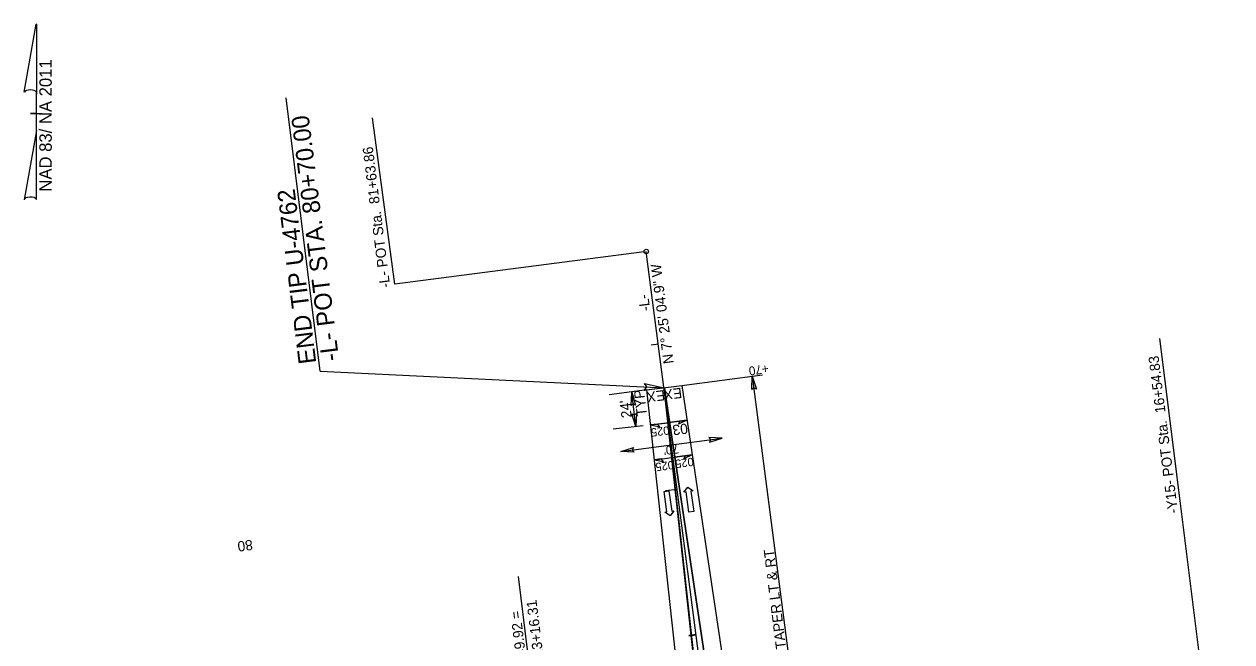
# Model space of a CAD drawing. Extents: x 2367848 to 2369479, y 800728 to 808616.
# Drawn here: x 2367890 to 2368715, y 808194 to 808616 of the extents above; entities that cross this region are included whole.
import ezdxf

# ---------------------------------------------------------------- set-up
doc = ezdxf.new("R2010")
doc.units = 0
for name, color, linetype in [('Prop Dimension', 7, 'Continuous'), ('Prop EOT', 7, 'Continuous'), ('Prop Horizontal Alignment', 7, 'Continuous'), ('Prop Horizontal Alignment Direction Label', 7, 'Continuous'), ('Prop Horizontal Alignment Station Label', 7, 'Continuous'), ('Prop Horizontal Alignment Tick Label', 7, 'Continuous'), ('Prop Horizontal Alignment Tick Large', 7, 'Continuous'), ('Prop Horizontal Alignment Tick Small', 7, 'Continuous'), ('Prop Lane Arrow CELL', 7, 'Continuous'), ('Prop Lane Lines', 7, 'Continuous'), ('Prop North Arrow NAD83 for Plan Sheets CELL', 7, 'Continuous'), ('Prop Paint Stripe', 7, 'Continuous'), ('Prop Superelevation  Arrow CELL', 7, 'Continuous'), ('Prop Superelevation Label', 7, 'Continuous'), ('Prop Terminator CELL', 7, 'Continuous')]:
    doc.layers.add(name, color=color, linetype=linetype)

msp = doc.modelspace()

# ---------------------------------------------------------------- linework, layer by layer
at = {"layer": 'Prop Dimension'}
for p, q in [((2368092.34, 808378.48), (2368069.05, 808565.34)), ((2368092.34, 808378.48), (2368327.36, 808367.26)), ((2368339.44, 808368.83), (2368394.74, 808376.03)), ((2368387.64, 808375.11), (2368426.37, 808077.62)), ((2368315.58, 808365.73), (2368289.84, 808362.37)), ((2368308.04, 808340.68), (2368305.28, 808364.22)), ((2368313.14, 808341.28), (2368292.68, 808338.88)), ((2368297.74, 808323.71), (2368367.15, 808332.75))]:
    msp.add_line(p, q, dxfattribs=at)
at = {"layer": 'Prop EOT'}
for p, q in [((2368315.58, 808365.73), (2368339.44, 808368.83)), ((2368348.25, 808067.45), (2368315.58, 808365.73)), ((2368339.44, 808368.83), (2368383.94, 808072.1))]:
    msp.add_line(p, q, dxfattribs=at)
at = {"layer": 'Prop Horizontal Alignment'}
msp.add_line((2368427.27, 807599.89), (2368315.24, 808460.34), dxfattribs=at)
at = {"layer": 'Prop Horizontal Alignment Station Label'}
for p, q in [((2368143.33, 808437.96), (2368128.09, 808551.49)), ((2368313.76, 808460.14), (2368143.33, 808437.96)), ((2368680.11, 808289.96), (2368666.29, 808400.85)), ((2368715.42, 808006.91), (2368680.11, 808289.96)), ((2368243.01, 808116.67), (2368227.83, 808238.43))]:
    msp.add_line(p, q, dxfattribs=at)
msp.add_circle((2368315.24, 808460.34), 1.5, dxfattribs=at)
at = {"layer": 'Prop Horizontal Alignment Tick Large'}
msp.add_line((2368336.4, 808297.85), (2368328.47, 808296.81), dxfattribs=at)
at = {"layer": 'Prop Horizontal Alignment Tick Small'}
for p, q in [((2368323.49, 808397.01), (2368318.53, 808396.36)), ((2368349.31, 808198.68), (2368344.35, 808198.04)), ((2368349.37, 808198.26), (2368344.41, 808197.61))]:
    msp.add_line(p, q, dxfattribs=at)
at = {"layer": 'Prop Lane Arrow CELL'}
for p, q in [((2368327.42, 808296.46), (2368330.69, 808296.92)), ((2368329.37, 808282.6), (2368327.42, 808296.46)), ((2368330.69, 808296.92), (2368332.64, 808283.06)), ((2368340.98, 808295.87), (2368343.6, 808299.43)), ((2368343.6, 808299.43), (2368347.21, 808296.75)), ((2368347.21, 808296.75), (2368345.73, 808296.55)), ((2368345.73, 808296.55), (2368347.68, 808282.68)), ((2368342.46, 808296.08), (2368340.98, 808295.87)), ((2368344.42, 808282.22), (2368342.46, 808296.08)), ((2368327.89, 808282.39), (2368329.37, 808282.6)), ((2368331.5, 808279.72), (2368327.89, 808282.39)), ((2368334.13, 808283.27), (2368331.5, 808279.72)), ((2368332.64, 808283.06), (2368334.13, 808283.27)), ((2368347.68, 808282.68), (2368344.42, 808282.22))]:
    msp.add_line(p, q, dxfattribs=at)
at = {"layer": 'Prop Lane Lines'}
for p, q in [((2368360.2, 808068.57), (2368327.53, 808366.85)), ((2368327.59, 808366.86), (2368372.04, 808070.55))]:
    msp.add_line(p, q, dxfattribs=at)
at = {"layer": 'Prop North Arrow NAD83 for Plan Sheets CELL'}
for p, q in [((2367890.15, 808569.2), (2367898.35, 808615.55)), ((2367898.4, 808615.55), (2367898.35, 808615.55)), ((2367898.4, 808615.55), (2367898.35, 808615.55)), ((2367898.4, 808615.55), (2367898.4, 808567.75)), ((2367898.4, 808542.95), (2367898.4, 808569.15)), ((2367898.4, 808567.75), (2367898.4, 808569.1)), ((2367894.4, 808554.55), (2367894.35, 808554.55)), ((2367897.95, 808554.55), (2367894.4, 808554.55)), ((2367894.45, 808554.55), (2367902.45, 808554.55)), ((2367898.4, 808542.95), (2367890.05, 808495.7)), ((2367898.45, 808495.9), (2367898.4, 808542.95))]:
    msp.add_line(p, q, dxfattribs=at)
for centre, start_param, end_param in [((2367894.29, 808568.71), 0.216388, 2.908219), ((2367894.29, 808495.54), 0.201328, 3.141593)]:
    msp.add_ellipse(centre, major_axis=(4.23, -0.03), ratio=0.461098, start_param=start_param, end_param=end_param, dxfattribs=at)
at = {"layer": 'Prop Paint Stripe'}
for p, q in [((2368327.59, 808366.86), (2368327.53, 808366.85)), ((2368327.59, 808366.86), (2368327.53, 808366.85)), ((2368327.53, 808366.85), (2368349.27, 808168.42)), ((2368372.04, 808070.55), (2368327.59, 808366.86)), ((2368372.04, 808070.55), (2368327.59, 808366.86))]:
    msp.add_line(p, q, dxfattribs=at)
msp.add_lwpolyline([(2368327.53, 808366.85), (2368349.27, 808168.42), (2368360.2, 808068.57)], dxfattribs=at)
at = {"layer": 'Prop Superelevation  Arrow CELL'}
for p, q in [((2368318.19, 808341.86), (2368330.09, 808343.41)), ((2368343, 808345.09), (2368331.1, 808343.54)), ((2368346.56, 808321.36), (2368334.66, 808319.81)), ((2368320.8, 808318), (2368332.7, 808319.55))]:
    msp.add_line(p, q, dxfattribs=at)
for points in [[(2368318.19, 808341.86), (2368324.4, 808340.65), (2368322.78, 808342.46)], [(2368343, 808345.09), (2368337.31, 808342.34), (2368338.42, 808344.5)], [(2368346.56, 808321.36), (2368340.87, 808318.6), (2368341.98, 808320.76)], [(2368320.8, 808318), (2368327.01, 808316.79), (2368325.39, 808318.6)]]:
    msp.add_lwpolyline(points, close=True, dxfattribs=at)
at = {"layer": 'Prop Superelevation Label'}
for p, q in [((2368318.19, 808341.86), (2368343, 808345.09)), ((2368320.8, 808318), (2368346.56, 808321.36))]:
    msp.add_line(p, q, dxfattribs=at)
at = {"layer": 'Prop Terminator CELL'}
for points in [[(2368387.4, 808365.98), (2368387.64, 808375.11), (2368390.52, 808366.38), (2368388.77, 808367.29)], [(2368304.79, 808355.1), (2368305.28, 808364.22), (2368307.92, 808355.42), (2368306.2, 808356.37)], [(2368313.98, 808370.17), (2368327.36, 808367.26), (2368313.7, 808365.45), (2368315.52, 808367.78)], [(2368308.53, 808349.8), (2368308.04, 808340.68), (2368305.4, 808349.48), (2368307.12, 808348.53)], [(2368358.4, 808330.15), (2368367.15, 808332.75), (2368357.98, 808333.27), (2368359.31, 808331.82)], [(2368306.86, 808323.34), (2368297.74, 808323.71), (2368306.5, 808326.47), (2368305.57, 808324.73)]]:
    msp.add_lwpolyline(points, close=True, dxfattribs=at)

# ---------------------------------------------------------------- texts
at = {"layer": 'Prop Dimension'}
for s, height, rotation, p in [('-L- POT STA. 80+70.00', 12, 97.10628, (2368105.34, 808386.14)), ('END TIP U-4762', 12, 97.10628, (2368089.73, 808384.2)), ('+70', 6, 187.76407, (2368398.45, 808383.34)), ('TYP', 7, 96.68066, (2368315.75, 808348.27)), ("24'", 7, 96.68066, (2368305.33, 808347.02)), ("70'", 6, 186.68066, (2368337.11, 808328.46)), ("300' LANE TAPER LT & RT", 7, 97.10628, (2368416.71, 808142.47))]:
    msp.add_text(s, height=height, rotation=rotation, dxfattribs=at).set_placement(p)
at = {"layer": 'Prop Horizontal Alignment Direction Label'}
msp.add_text('N 7%%d 25\' 04.9" W', height=7, rotation=97.41804, dxfattribs=at).set_placement((2368334.01, 808384.06))
at = {"layer": 'Prop Horizontal Alignment Station Label'}
for s, rotation, p in [('-L- POT Sta.  81+63.86', 97.10628, (2368140.26, 808435.96)), ('-L-', 97.41804, (2368318.01, 808420.08)), ('-Y15- POT Sta.  16+54.83', 97.10628, (2368678.73, 808281.8)), ('-Y15- POT Sta.  13+16.31', 97.10628, (2368253.55, 808115.06)), ('-L- POT Sta. 76+49.92 = ', 97.10628, (2368241.85, 808113.48))]:
    msp.add_text(s, height=7, rotation=rotation, dxfattribs=at).set_placement(p)
at = {"layer": 'Prop Horizontal Alignment Tick Label'}
msp.add_text('80', height=7, rotation=187.41804, dxfattribs=at).set_placement((2368045.8, 808263.54))
at = {"layer": 'Prop North Arrow NAD83 for Plan Sheets CELL'}
msp.add_text('NAD 83/ NA 2011', height=8.5, rotation=89.99998, dxfattribs=at).set_placement((2367908.92, 808501.2))
at = {"layer": 'Prop Superelevation Label'}
for s, height, rotation, p in [('EX', 7, 187.10628, (2368327.57, 808365.75)), ('EX', 7, 187.10628, (2368339.16, 808367.33)), ('025', 5.67, 187.41804, (2368330.62, 808341.02)), ('03', 7, 187.41804, (2368343.12, 808342.99)), ('025', 5.67, 187.41804, (2368333.72, 808317.44)), ('025', 5.67, 187.41804, (2368347.22, 808319.6))]:
    msp.add_text(s, height=height, rotation=rotation, dxfattribs=at).set_placement(p)

doc.saveas('drawing.dxf')
